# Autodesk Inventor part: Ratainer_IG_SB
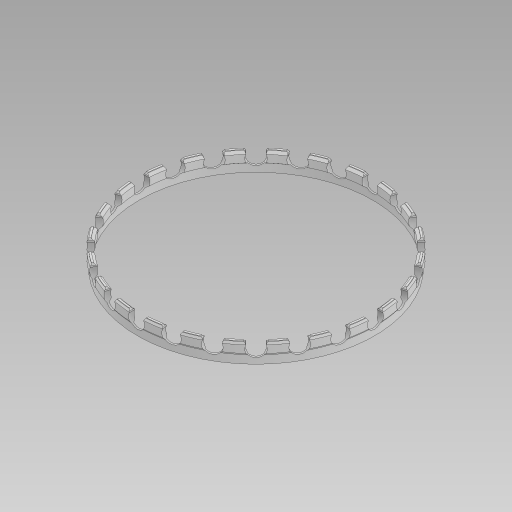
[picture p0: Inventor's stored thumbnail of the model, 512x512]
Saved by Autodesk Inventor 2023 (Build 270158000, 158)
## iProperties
Created: 2024-05
Part Number: Ratainer_IG_SB
Material: 一般
Document SubType Name: Modeling
Designer: kumagai
Density: 1 g/cm^3
Appearance: 既定
Author: kumagai
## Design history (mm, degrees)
derived "CoreSketch.ipt"
  sketch "Vertical"
    geometry: L1 (0, 65.337)-(0, -65.337) reference; L2 (-46.2, 0)-(46.2, 0) reference; L3 (-11, 2)-(11, 2) reference; L4 (11, 2)-(11, -2) reference; L5 (11, -2)-(-11, -2) reference; L6 (-11, -2)-(-11, 2) reference; L7 (11, 2)-(33, 2) reference; L8 (33, 2)-(33, -2) reference; L9 (33, -2)-(11, -2) reference; L10 (11, -2)-(11, 2) reference; L11 (22, 2.772)-(22, -2.683) reference; L12 (-33, 2)-(-11, 2) reference; L13 (-11, 2)-(-11, -2) reference; L14 (-11, -2)-(-33, -2) reference; L15 (-33, -2)-(-33, 2) reference; L16 (-22, 4.087)-(-22, -4.199) reference; L17 (-33, 10)-(-11, 10) reference; L18 (-11, 10)-(-11, 6) reference; L19 (-11, 6)-(-33, 6) reference; L20 (-33, 6)-(-33, 10) reference; L21 (-27.353, 10)-(-16.647, 10) reference; L22 (-16.647, 10)-(-16.647, 16) reference; L23 (-16.647, 16)-(-27.353, 16) reference; L24 (-27.353, 16)-(-27.353, 10) reference; L25 (11, 16)-(33, 16) reference; L26 (33, 16)-(33, 12) reference; L27 (33, 12)-(11, 12) reference; L28 (11, 12)-(11, 16) reference; L29 (16.134, 12)-(27.866, 12) reference; L30 (27.866, 12)-(27.866, 6) reference; L31 (27.866, 6)-(16.134, 6) reference; L32 (16.134, 6)-(16.134, 12) reference; L33 (-22, 18.272)-(-22, 9.031) reference; L34 (22, 22.635)-(22, 12.71) reference; L35 (33, -2)-(35, -2) reference; L36 (35, -2)-(35, 10) reference; L37 (35, 10)-(33, 10) reference; L38 (33, 10)-(33, -2) reference; L39 (0, -4)-(37.5, -4) reference; L40 (40.5, -1)-(40.5, 14) reference; L41 (43.9, -8)-(0, -8) reference; L42 (0, -4)-(0, -8) reference; L43 (35, -2)-(39, -2) reference; L44 (39, -2)-(39, 3.066) reference; L45 (38.45, 8.685)-(41.471, 10.429) reference; L46 (38.45, 10)-(35, 10) reference; L47 (40.5, 9.627)-(41.993, 8.375) reference; L48 (41.55, 3.315)-(40.5, 2.709) reference; L49 (37.5, -4)-(40.5, -1) reference; L50 (-43, 43.294)-(-1, 43.294) reference; L51 (-1, 43.294)-(-1, 26) reference; L52 (-1, 26)-(-43, 26) reference; L53 (-43, 26)-(-43, 43.294) reference; L54 (1, 43.294)-(43, 43.294) reference; L55 (43, 43.294)-(43, 26) reference; L56 (43, 26)-(1, 26) reference; L57 (1, 26)-(1, 43.294) reference; L58 (-22, 45.556)-(-22, 31.232) reference; L59 (22, 47.214)-(22, 32.287) reference; L60 (48, 5.268)-(48, -2.616) reference; L61 (43.6, -11)-(54, -11) reference; L62 (54, -11)-(54, 18) reference; L63 (45.222, -3.461)-(46.5, -2.566) reference; L64 (48, -2.616)-(49.192, -3.808) reference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; A1 r 3.1 centre (40, 6) between (39, 3.066) and (38.45, 8.685) reference; A2 r 3.1 centre (47, -6) between (45.222, -3.461) and (49.192, -3.808) reference; A3 r 3.1 centre (47, 13) between (43.9, 13) and (49, 10.631) reference; 2 further points; 1 other entity
    constraints: 1 other
sketch "スケッチ3"
  geometry: L1 (0, -66.64)-(0, 66.64) reference; A1 r 46.9 centre (0, 0) between (-46.9, 0) and (0, -46.9); 11 further points
  constraints: 2 coincident, 2 point on circle, 2 point on line, 1 centre point, 1 vertical alignment, 4 other
  dimensions: "d3" = 0.7 dimension on A1; "d27" = 0.4 distance of point (-46.5, 0) A1.start
extrude "押し出し1" new body sketch "スケッチ3" distance "d6" = 8; taper "d7" = 0 deg
sketch "スケッチ4"
  geometry: L1 (8, -47.6)-(8, 47.6) reference; L2 (0, -47.6)-(0, 47.6) reference; L3 (0, 66.22)-(0, -66.22) reference; L4 (-24.112, 0)-(59.102, 0) reference; L5 (8, 3.5)-(8, -3.5); L6 (8, -3.5)-(7.297, -2.98); L7 (7.297, 2.98)-(8, 3.5); A1 r 3.2 centre (5.5, 0) between (6.797, 2.925) and (6.797, -2.925); A2 r 0.5 centre (7, 3.382) between (6.797, 2.925) and (7.297, 2.98); A3 r 0.5 centre (7, -3.382) between (7.297, -2.98) and (6.797, -2.925); 5 further points
  constraints: 6 end point, 6 point on circle, 4 tangent, 3 centre point, 1 equal radius, 1 point on line, 1 symmetric about line, 1 vertical alignment
  dimensions: "d9" = 5.5 distance from line of A1.centre L2; "d13" = 0.5 radius of A2; "d19" = 3.2 radius of A1; "d21" = 8 distance between parallel lines of L2 L5; "d22" = 3.5 distance from line of L5.end L4; "d23" = 2.5 distance from line of A1.centre L5 (derived); "d24" = 1.5 horizontal distance of A3.centre A1.centre; "d25" = 6.76461 distance of A3.centre A2.centre (derived); "d26" = 5.76461 dimension on A3 A2 (derived)
sketch "スケッチ7"
  geometry: L1 (7, -45.9)-(4, -45.9); L2 (7, -45.9)-(7.75, -46.9); L3 (7.75, -46.9)-(7.75, -47.6); L4 (4, -45.9)-(3.25, -46.9); L5 (3.25, -46.9)-(3.25, -47.6); L6 (5.5, -49.264)-(5.5, -50.635); L7 (7.75, -47.6)-(3.25, -47.6); L8 (-24.112, 0)-(59.102, 0) reference; L9 (7.75, -47.6)-(7, -48.1); L10 (7, -48.1)-(4, -48.1); L11 (4, -48.1)-(3.25, -47.6); 3 further points
  constraints: 20 end point, 4 horizontal alignment, 2 vertical alignment, 1 horizontal, 1 symmetric about line, 1 vertical, 1 other
  dimensions: "d28" = 1 distance from line of L1 point (0, -46.9); "d30" = 5.5 distance from line of point (0, -47.6) L6; "d32" = 4.5 distance between parallel lines of L5 L3; "d33" = 3 distance of L1.end L1.start; "d35" = 0.5 distance between parallel lines of L7 L10
revolve "回転1" sketch "スケッチ7" stored, may be unused: angle "d34" = 360 deg
extrude "押し出し3" cut sketch "スケッチ4" extent not by distance; stored distance "d14" = 0; taper "d15" = 0 deg
pattern_circular "円形状パターン1" dims angle "d17" = 180 deg
node "ソリッド1"
